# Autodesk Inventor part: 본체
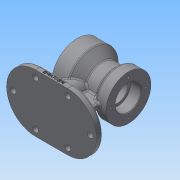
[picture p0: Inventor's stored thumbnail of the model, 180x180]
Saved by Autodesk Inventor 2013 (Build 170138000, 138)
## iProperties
Created: 2020-01
Part Number: 본체
Material: 일반
Document SubType Name: Modeling
Designer: Administrator
Density: 1 g/cm^3
Author: Administrator
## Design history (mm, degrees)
sketch "스케치1"
  geometry: L1 (-40, 0)-(40, 0); L2 (-40, 40)-(-40, 0); L3 (-40, 40)-(-16, 40); L4 (-16, 40)-(-1.103, 27.5); L5 (-1.103, 27.5)-(17.707, 27.5); L6 (17.707, 27.5)-(24, 35); L7 (24, 35)-(40, 35); L8 (40, 35)-(40, 0); 2 further points
  constraints: 16 end point, 4 perpendicular, 2 coincident, 2 midpoint, 2 parallel, 1 horizontal
  dimensions: "d0" = 80 distance between parallel lines of L8 L2; "d2" = 55 diameter of L5 L1; "d4" = 24 distance of L2.start L3.end; "d5" = 80 diameter of L3 L1; "d6" = 40 deg angle of L4 L5; "d8" = 70 diameter of L7 L1; "d10" = 16 distance of L6.end L7.end
revolve "회전1" sketch "스케치1" stored, may be unused: angle "d11" = 90 deg
sketch "스케치2"
  geometry: C1 r 35 at (0, 0) reference; C2 r 20 at (0, 0)
  constraints: 1 centre point, 1 coincident
  dimensions: "d12" = 40 diameter of C2
extrude "돌출1" cut sketch "스케치2" distance "d13" = 17; taper "d14" = 0 deg
sketch "스케치3"
  geometry: C1 r 20 at (0, 0) reference; C2 r 16 at (0, 0)
  constraints: 1 centre point, 1 coincident
  dimensions: "d15" = 32 diameter of C2
extrude "돌출2" cut sketch "스케치3" stored distance "d16" = 17; taper "d17" = 0 deg
sketch "스케치4"
  geometry: C1 r 16 at (0, 0) reference; C2 r 40 at (0, 0) reference; C3 r 26 at (0, 0)
  constraints: 1 centre point, 1 coincident
  dimensions: "d18" = 52 diameter of C3
extrude "돌출3" cut sketch "스케치4" distance "d19" = 20; taper "d20" = 0 deg
sketch "스케치5"
  geometry: C1 r 26 at (0, 0) reference; 1 further point
  constraints: 1 vertical alignment
  dimensions: "d21" = 33 distance of point (0, 33) C1.centre
hole "구멍1" sketch "스케치5" at (0, 33) diameter "d22" = 3.242; stored, may be unused: countersink angle "d26" = 90 deg, drill point angle "d28" = 118 deg; dims "d23" = 9, "d24" = 4, "d25" = 2, "d27" = 11
sketch "스케치6"
  geometry: C1 r 20 at (0, 0) reference; 1 further point
  constraints: 1 vertical alignment
  dimensions: "d32" = 27.5 distance of C1.centre point (0, 27.5)
hole "구멍2" sketch "스케치6" at (0, 27.5) diameter "d33" = 3.242; stored, may be unused: countersink angle "d37" = 90 deg, drill point angle "d39" = 118 deg; dims "d34" = 9, "d35" = 4, "d36" = 2, "d38" = 11
sketch "스케치7"
  geometry: L1 (-70, -45)-(-80, -45); L2 (-80, -45)-(-80, 45); L3 (-80, 45)-(-70, 45); L4 (-70, 45)-(-70, -45); 2 further points
  constraints: 8 end point, 2 parallel, 1 horizontal, 1 horizontal alignment, 1 midpoint, 1 perpendicular
  dimensions: "d43" = 90 distance of L1.end L2.end; "d45" = 10 distance of L2.end L3.end; "d46" = 80 distance from line of L2 point (0, 0)
extrude "돌출4" join sketch "스케치7" stored distance "d47" = 140; taper "d48" = 0 deg
fillet "모깎기1" dims "d49" = 45
sketch "스케치8"
  geometry: L1 (0, 0)-(50, 0) reference; L2 (50, -90)-(0, -90) reference; L3 (0, -10)-(50, -10); L4 (50, -80)-(0, -80); L5 (-0.767, -45)-(-45, -45); L6 (20, -40)-(55, -40); L7 (55, -40)-(55, -50); L8 (55, -50)-(20, -50); L9 (20, -50)-(20, -40); C1 r 16 at (13, -45); C2 r 4.5 at (0, -10); C3 r 4.5 at (-35, -45); A1 r 45 centre (50, -45) between (50, -90) and (50, 0) reference; A2 r 45 centre (0, -45) between (0, 0) and (0, -90) reference; A3 r 45 centre (0, -45) between (0, 0) and (0, -90) reference; A4 r 35 centre (0, -45) between (0, -10) and (0, -80); A5 r 35 centre (50, -45) between (50, -80) and (50, -10); 5 further points
  constraints: 14 end point, 6 point on circle, 5 centre point, 4 coincident, 3 parallel, 2 horizontal alignment, 1 horizontal, 1 midpoint, 1 perpendicular, 1 point on line, 2 other
  dimensions: "d50" = 10 distance between parallel lines of L3 L1; "d51" = 10 radial gap between concentric circles of A2 A4; "d52" = 58 distance of point (13, -45) L5.end; "d53" = 32 diameter of C1; "d54" = 9 diameter of C2; "d55" = 9 diameter of C3; "d58" = 30 distance from line of L7 point (25, -45); "d59" = 10 distance of L6.end L7.end; "d60" = 35 distance between parallel lines of L7 L9
extrude "돌출5" cut sketch "스케치8" distance "d56" = 10; taper "d57" = 0 deg
extrude "돌출6" join sketch "스케치8" stored distance "d61" = 10; taper "d62" = 0 deg
fillet "모깎기2" dims "d63" = 0.3
chamfer "모따기1" distance "d64" = 1; stored, may be unused: second distance "d65" = 2, angle "d66" = 45 deg
fillet "모깎기3" dims "d67" = 3
fillet "모깎기4" dims "d68" = 3
fillet "모깎기5" dims "d69" = 3
sketch "스케치10"
  geometry: L1 (50, 0)-(0, 0) reference; L2 (-45, 0)-(-45, 7) reference; 2 further points
  constraints: 1 other
  dimensions: "d74" = 4 distance from line of L1 point (25, 4); "d75" = 70 distance from line of point (25, 4) L2
feature "엠보싱2" sketch "스케치10" dims "d15" = 32, "d76" = 0.5, "d77" = 0
node "솔리드1"
pattern_circular "원형 패턴1" dims angle "d30" = 360 deg
pattern_circular "원형 패턴2" dims angle "d41" = 360 deg
mirror "대칭1"
mirror "대칭2"
